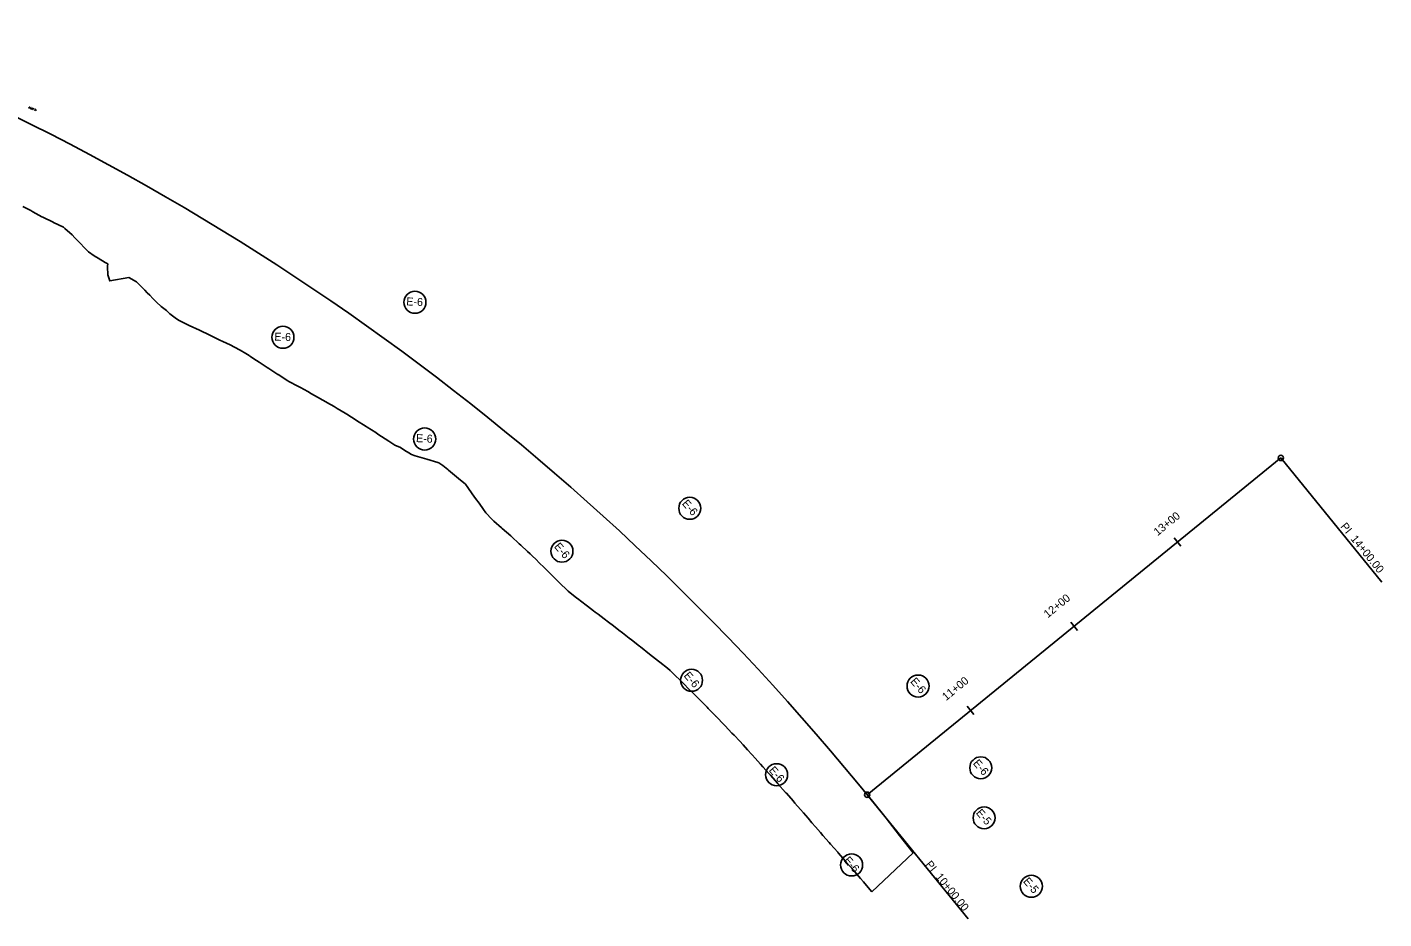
# Model space of a CAD drawing. Extents: x 881727 to 890277, y 1562105 to 1567179.
# Drawn here: x 882733 to 883751, y 1566368 to 1567037 of the extents above; entities that cross this region are included whole.
import ezdxf

# ---------------------------------------------------------------- set-up
doc = ezdxf.new("R2010")
doc.units = 0
for name, color, linetype in [('22', 7, 'Continuous'), ('Default', 7, 'Continuous'), ('R_Axis Annot', 7, 'Continuous'), ('R_Grid', 7, 'Continuous'), ('R_Water', 7, 'Continuous')]:
    doc.layers.add(name, color=color, linetype=linetype)

msp = doc.modelspace()

# ---------------------------------------------------------------- linework, layer by layer
at = {"layer": '22'}
msp.add_line((883397.7, 1566417.8), (883366.9, 1566388.6), dxfattribs=at)
for points in [[(882793.8, 1566859.2), (882792, 1566860.4), (882786.6, 1566863.6), (882783.7, 1566865.2), (882779.4, 1566868.3), (882776.2, 1566871.6), (882773.3, 1566874.6), (882771.6, 1566876.3), (882769.1, 1566878.9), (882767.1, 1566881), (882761.8, 1566885.8), (882760.6, 1566886.9), (882753.3, 1566890.3), (882752.9, 1566890.5), (882745.2, 1566894.3), (882744.5, 1566894.6), (882737.8, 1566898.3), (882736.1, 1566899.3), (882730.2, 1566902.2)], [(882809.7, 1566849.1), (882795.3, 1566846.5), (882794, 1566851.1), (882793.9, 1566852), (882793.8, 1566853.1), (882793.6, 1566855), (882793.6, 1566857), (882793.6, 1566857.5), (882793.8, 1566859.2)], [(883366.9, 1566388.6), (883364, 1566391.9), (883360.5, 1566396.1), (883358.4, 1566398.4), (883354, 1566403.5), (883352.8, 1566404.9), (883347.6, 1566410.8), (883347.1, 1566411.4), (883341.5, 1566417.8), (883341.2, 1566418.2), (883335.8, 1566424.3), (883334.7, 1566425.5), (883330.1, 1566430.7), (883328.2, 1566432.9), (883324.5, 1566437.2), (883321.9, 1566440.3), (883319, 1566443.7), (883315.5, 1566447.7), (883313.4, 1566450.2), (883309.1, 1566455.1), (883307.7, 1566456.7), (883302.7, 1566462.4), (883302.1, 1566463.1), (883296.4, 1566469.5), (883296.3, 1566469.7), (883290.8, 1566476), (883289.8, 1566477), (883285.1, 1566482.3), (883283.3, 1566484.3), (883279.3, 1566488.7), (883277.1, 1566491.2), (883276.8, 1566491.6), (883273.6, 1566495), (883270.2, 1566498.8), (883267.8, 1566501.4), (883263.5, 1566505.9), (883261.8, 1566507.5), (883256.8, 1566512.9), (883256, 1566513.8), (883250, 1566519.9), (883250, 1566519.9), (883244.1, 1566526), (883243.2, 1566527), (883238.1, 1566532.1), (883236.3, 1566533.9), (883232, 1566538.2), (883229.4, 1566540.8), (883226, 1566544.3), (883222.6, 1566547.7), (883219.9, 1566550.3), (883215.6, 1566554.5), (883213.6, 1566556.1), (883207.9, 1566560.6), (883206.9, 1566561.5), (883200.2, 1566566.7), (883200.1, 1566566.8), (883193.4, 1566572.1), (883192.5, 1566572.8), (883186.6, 1566577.4), (883184.8, 1566578.8), (883179.8, 1566582.7), (883177.1, 1566584.8), (883173, 1566587.9), (883169.3, 1566590.8), (883166.2, 1566593.1), (883161.6, 1566596.7), (883159.4, 1566598.3), (883158.1, 1566599.3), (883153.7, 1566602.6), (883152.5, 1566603.5), (883146, 1566608.4), (883145.7, 1566608.6), (883139, 1566613.9), (883138.4, 1566614.6), (883132.9, 1566619.8), (883131.4, 1566621.3), (883126.9, 1566625.9), (883124.6, 1566628.2), (883120.8, 1566631.8), (883117.7, 1566635), (883114.8, 1566637.8), (883112.3, 1566640.2), (883110.7, 1566641.8), (883108.6, 1566643.7), (883103.6, 1566648.3), (883102.3, 1566649.4), (883096.5, 1566654.9), (883096.1, 1566655.3), (883089.7, 1566660.9), (883089.2, 1566661.3), (883083.4, 1566666.5), (883081.9, 1566667.8), (883077.3, 1566672.6), (883075.5, 1566675.2), (883072.3, 1566679.8), (883069.7, 1566683.4), (883067.2, 1566687), (883063.9, 1566691.7), (883062, 1566694.2), (883056.9, 1566698.5), (883055.4, 1566699.7), (883049.4, 1566704.7), (883048.9, 1566705.1), (883045.1, 1566708.2), (883042, 1566710.2), (883041.4, 1566710.4), (883033.1, 1566712.8), (883031.3, 1566713.3), (883024.3, 1566715.3), (883021.5, 1566716.5), (883019.6, 1566717.6), (883016.7, 1566719.5), (883013.3, 1566721.7), (883009.1, 1566723.5), (883004.7, 1566726.4), (883001.9, 1566728.1), (882996.5, 1566731.7), (882994.8, 1566732.8), (882988.4, 1566736.9), (882987.6, 1566737.4), (882980.5, 1566741.9), (882980.2, 1566742.1), (882973.2, 1566746.5), (882971.9, 1566747.3), (882966, 1566750.9), (882963.6, 1566752.3), (882958.6, 1566755.2), (882955.7, 1566756.9), (882955.2, 1566757.1), (882951.2, 1566759.4), (882946.7, 1566761.9), (882943.8, 1566763.6), (882938.3, 1566766.6), (882936.3, 1566767.7), (882929.7, 1566771.2), (882928.8, 1566771.7), (882921.7, 1566776.3), (882921.5, 1566776.4), (882914.6, 1566780.9), (882913.5, 1566781.6), (882907.5, 1566785.5), (882905.4, 1566786.9), (882900.4, 1566790.1), (882899.8, 1566790.5), (882897.3, 1566792.1), (882893.2, 1566794.6), (882888.9, 1566796.9), (882885.6, 1566798.5), (882880.2, 1566801.2), (882878, 1566802.2), (882871.4, 1566805.4), (882870.3, 1566805.9), (882862.7, 1566809.6), (882862.7, 1566809.6), (882855, 1566813.2), (882853.9, 1566813.7), (882847.3, 1566816.9), (882845.4, 1566818.2), (882840.5, 1566821.9), (882837.9, 1566824.4), (882834, 1566827.4), (882830.4, 1566830.5), (882827.6, 1566833.3), (882825.3, 1566835.8), (882823.5, 1566837.7), (882821.6, 1566839.7), (882816.5, 1566844.8), (882815.4, 1566845.8), (882809.7, 1566849.1)]]:
    msp.add_lwpolyline(points, dxfattribs=at)
msp.add_arc((881881.9, 1565255.8), 1909.9, 37.4722, 68.8256, dxfattribs=at)
at = {"layer": 'Default'}
msp.add_circle((882925.2, 1566804.3), 8.26, dxfattribs=at)
at = {"layer": 'R_Axis Annot'}
msp.add_line((883363.3, 1566461.3), (883673.5, 1566713.8), dxfattribs=at)
at = {"layer": 'R_Grid'}
for points in [[(883673.5, 1566713.8), (883749.2, 1566620.7)], [(883593.4, 1566653.8), (883598.5, 1566647.6)], [(883515.9, 1566590.7), (883520.9, 1566584.5)], [(883438.3, 1566527.6), (883443.3, 1566521.4)], [(883363.3, 1566461.3), (883439, 1566368.3)]]:
    msp.add_lwpolyline(points, dxfattribs=at)
for centre in [(883673.5, 1566713.8), (883363.3, 1566461.3)]:
    msp.add_circle(centre, 2, dxfattribs=at)
at = {"layer": 'R_Water'}
for p, q in [((882734.4, 1566975.9), (882735.6, 1566977)), ((882735.4, 1566975.5), (882736.7, 1566976.6)), ((882736.5, 1566975.1), (882737.7, 1566976.3)), ((882737.5, 1566974.7), (882738.8, 1566975.9)), ((882738.6, 1566974.3), (882739.9, 1566975.5)), ((882739.7, 1566973.9), (882740.5, 1566974.7))]:
    msp.add_line(p, q, dxfattribs=at)
for centre in [(883024.2, 1566830.5), (883031.5, 1566728), (883230.3, 1566676.1), (883134.4, 1566643.9), (883231.6, 1566547.1), (883401.5, 1566542.8), (883295.4, 1566476.3), (883448.5, 1566481.5), (883451, 1566444), (883351.6, 1566408.7), (883486.4, 1566392.7)]:
    msp.add_circle(centre, 8.26, dxfattribs=at)

# ---------------------------------------------------------------- texts
at = {"layer": 'Default'}
msp.add_text('E-6 ', height=6, rotation=358.2162, dxfattribs=at).set_placement((882918.7, 1566801.8))
at = {"layer": 'R_Grid'}
for s, rotation, p in [('13+00', 39.1387, (883581.1, 1566655.1)), ('PI  14+00.00', 309.1387, (883717.9, 1566662.3)), ('12+00', 39.1387, (883498.7, 1566593.5)), ('11+00', 39.1387, (883422.5, 1566531.5)), ('PI  10+00.00', 309.1387, (883406.6, 1566408.9))]:
    msp.add_text(s, height=6, rotation=rotation, dxfattribs=at).set_placement(p)
at = {"layer": 'R_Water'}
for s, rotation, p in [('E-6 ', 357.2872, (883017.6, 1566828.2)), ('E-6 ', 357.2872, (883024.9, 1566725.7)), ('E-6 ', 310.5862, (883224.1, 1566679.4)), ('E-6 ', 310.5862, (883128.2, 1566647.2)), ('E-6 ', 310.5862, (883225.4, 1566550.4)), ('E-6 ', 310.5862, (883395.3, 1566546)), ('E-6 ', 310.5862, (883289.2, 1566479.5)), ('E-6 ', 310.5862, (883442.3, 1566484.7)), ('E-5 ', 310.5862, (883444.5, 1566447.5)), ('E-6 ', 310.5862, (883345.4, 1566411.9)), ('E-5 ', 310.5862, (883479.9, 1566396.2))]:
    msp.add_text(s, height=6, rotation=rotation, dxfattribs=at).set_placement(p)

doc.saveas('drawing.dxf')
